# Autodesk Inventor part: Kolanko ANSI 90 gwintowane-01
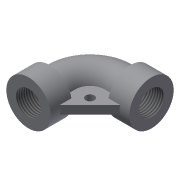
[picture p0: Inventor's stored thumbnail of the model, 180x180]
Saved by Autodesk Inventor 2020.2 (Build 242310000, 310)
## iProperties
Created: 2014-08
Part Number: Kolanko ANSI 90 gwintowane-01
Material: Ogólny
Document SubType Name: Modeling
Designer: F.Stasiak
Density: 1 g/cm^3
Appearance: Domyślna
Categories: <MemberInstance><Categories><Category DisplayName="" InternalName="4347fa0f-2144-441d-94cd-e3e15c92b736" Mnemonic="TUBEANDPIPE"><CategoryParameter DisplayName="
Catalog Web Link: www.expertbooks.pl
Manager: www.cadconsulting.pl
Company: Fabian Stasiak CAD Consulting
Author: F.Stasiak
Subject: Zbiór ćwiczeń. Autodesk Inventor 2020. Kurs Professional
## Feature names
1. Przeciągnięcie1
2. Wyciągnięcie proste1 [Extrusion]
3. Wyciągnięcie proste2 [Extrusion]
4. Wyciągnięcie proste5 [Extrusion]
## Parameters: d0 = 45.7835 mm, d1 = 45.7835 mm, d2 = 22.89175 mm, d4 = 0, d5 = 0, d6 = 33.02 mm, d7 = 18.3134 mm, d9 = 15.748 mm, d10 = 0, d11 = 33.02 mm, d12 = 15.748 mm, d13 = 0, d19 = 19.8628 mm, d20 = 0, d21 = 19.8628 mm, d22 = 0, ID = 18.3134 mm, OD = 33.02 mm, GL = 15.748 mm, G = 3.175 mm, d23 = 3.175 mm, d24 = 6.35 mm, d26 = 6.35 mm, d27 = 0
